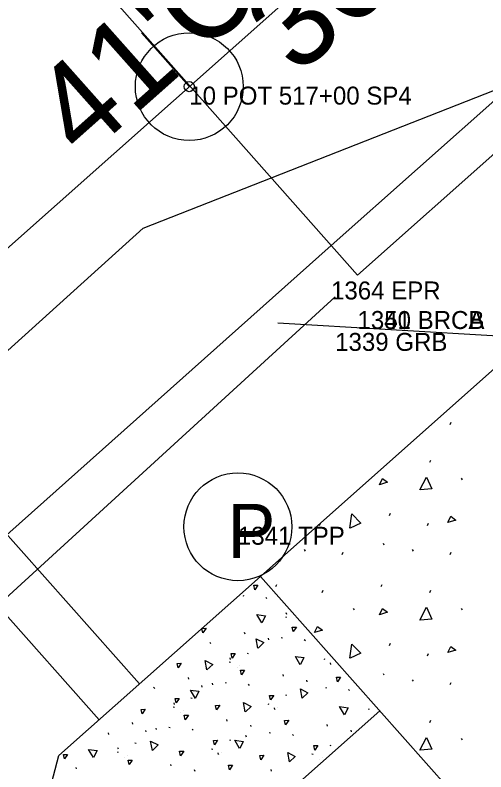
# Model space of a CAD drawing. Extents: x 50001 to 56005, y 49075 to 53926.
# Drawn here: x 53432.14 to 53458.33, y 51442.52 to 51484.63 of the extents above; entities that cross this region are included whole.
import ezdxf

# ---------------------------------------------------------------- set-up
doc = ezdxf.new("R2010")
doc.units = 0
for name, color, linetype in [('Level 1', 7, 'Continuous'), ('Level 15', 7, 'Continuous'), ('Level 18', 7, 'Continuous'), ('Level 20', 7, 'Continuous'), ('Level 3', 7, 'Continuous'), ('Level 5', 7, 'Continuous'), ('Level 51', 7, 'Continuous'), ('Level 53', 7, 'Continuous'), ('Level 55', 7, 'Continuous'), ('Level 57', 7, 'Continuous'), ('Level 59', 7, 'Continuous'), ('Level 7', 7, 'Continuous'), ('Level 8', 7, 'Continuous'), ('Level 9', 7, 'Continuous')]:
    doc.layers.add(name, color=color, linetype=linetype)

# ---------------------------------------------------------------- blocks, each defined once
blk = doc.blocks.new('PC')
at = {"layer": 'Level 1'}
for radius in [3, 0.282]:
    blk.add_circle((0, 0), radius, dxfattribs=at)
blk = doc.blocks.new('TPP')
at = {"layer": 'Level 9'}
blk.add_circle((0, 0), 3, dxfattribs=at)
blk.add_text('P', height=3, dxfattribs=at).set_placement((-0.589, -1.729))

msp = doc.modelspace()

# ---------------------------------------------------------------- linework, layer by layer
at = {"layer": 'Level 1'}
for p, q in [((52544.807, 50683.302), (55534.583, 53340.862)), ((53441.831, 51480.651), (53439.174, 51483.64))]:
    msp.add_line(p, q, dxfattribs=at)
at = {"layer": 'Level 15'}
for p, q in [((53446.758, 51467.502), (53460.734, 51466.679)), ((53445.785, 51453.392), (53460.734, 51466.679)), ((53456.338, 51461.856), (53456.394, 51461.981)), ((53455.214, 51459.747), (53455.27, 51459.872)), ((53456.949, 51458.859), (53457.004, 51458.776)), ((53452.967, 51456.792), (53453.022, 51456.917)), ((53449.076, 51456.223), (53449.131, 51456.348)), ((53455.076, 51456.223), (53455.131, 51456.348)), ((53452.608, 51455.238), (53452.663, 51455.155)), ((53448.227, 51454.885), (53448.282, 51454.802)), ((53450.338, 51454.614), (53450.394, 51454.738)), ((53454.227, 51454.885), (53454.282, 51454.802)), ((53456.338, 51454.614), (53456.394, 51454.738)), ((53475.017, 51420.506), (53445.785, 51453.392)), ((53446.646, 51452.824), (53446.701, 51452.949)), ((53449.214, 51452.505), (53449.27, 51452.63)), ((53452.503, 51452.824), (53452.558, 51452.949)), ((53455.214, 51452.505), (53455.27, 51452.63)), ((53450.949, 51451.617), (53451.004, 51451.534)), ((53456.949, 51451.617), (53457.004, 51451.534)), ((53452.967, 51449.549), (53453.022, 51449.674)), ((53455.076, 51448.98), (53455.131, 51449.105)), ((53452.608, 51447.996), (53452.663, 51447.912)), ((53454.227, 51447.643), (53454.282, 51447.559)), ((53456.338, 51447.371), (53456.394, 51447.496)), ((53455.214, 51445.262), (53455.27, 51445.387)), ((53456.949, 51444.374), (53457.004, 51444.291))]:
    msp.add_line(p, q, dxfattribs=at)
for points in [[(53454.663, 51458.209), (53455.037, 51458.916), (53455.329, 51458.264), (53454.676, 51458.209)], [(53452.406, 51458.499), (53452.572, 51458.846), (53452.85, 51458.637), (53452.406, 51458.499)], [(53450.764, 51456.08), (53450.874, 51456.873), (53451.371, 51456.359), (53450.777, 51456.084)], [(53456.219, 51456.393), (53456.385, 51456.74), (53456.663, 51456.532), (53456.219, 51456.393)], [(53452.406, 51451.256), (53452.572, 51451.603), (53452.85, 51451.395), (53452.406, 51451.256)], [(53454.663, 51450.966), (53455.037, 51451.674), (53455.329, 51451.022), (53454.676, 51450.966)], [(53448.801, 51450.264), (53448.967, 51450.611), (53449.245, 51450.403), (53448.801, 51450.264)], [(53450.764, 51448.837), (53450.874, 51449.63), (53451.371, 51449.117), (53450.777, 51448.842)], [(53456.219, 51449.151), (53456.385, 51449.497), (53456.663, 51449.289), (53456.219, 51449.151)], [(53454.663, 51443.724), (53455.037, 51444.431), (53455.329, 51443.779), (53454.676, 51443.724)]]:
    msp.add_lwpolyline(points, dxfattribs=at)
at = {"layer": 'Level 18'}
for p, q in [((53439.259, 51472.776), (53468.056, 51484.091)), ((53402.158, 51439.255), (53439.259, 51472.776))]:
    msp.add_line(p, q, dxfattribs=at)
at = {"layer": 'Level 20'}
msp.add_line((52706.174, 50782.585), (53452.429, 51445.918), dxfattribs=at)
at = {"layer": 'Level 3'}
for p, q in [((53449.718, 51471.806), (53898.742, 51870.567)), ((53179.352, 51230.724), (53449.718, 51471.806))]:
    msp.add_line(p, q, dxfattribs=at)
at = {"layer": 'Level 5'}
for p, q in [((53900.074, 51869.402), (53451.19, 51470.163)), ((53451.19, 51470.163), (53432.563, 51491.203))]:
    msp.add_line(p, q, dxfattribs=at)
at = {"layer": 'Level 7'}
msp.add_line((53424.8, 51445.953), (53449.946, 51468.944), dxfattribs=at)
at = {"layer": 'Level 8'}
for p, q in [((53439.059, 51447.413), (53426.275, 51461.794)), ((53436.816, 51445.42), (53424.28, 51459.523)), ((53445.785, 51453.392), (53434.574, 51443.427)), ((53444.806, 51452.333), (53444.87, 51452.313)), ((53446.091, 51452.225), (53446.15, 51452.165)), ((53447.249, 51451.275), (53447.225, 51451.363)), ((53447.179, 51451.14), (53447.242, 51451.12)), ((53444.93, 51450.18), (53444.907, 51450.269)), ((53442.969, 51449.724), (53443.028, 51449.665)), ((53446.258, 51449.869), (53446.235, 51449.957)), ((53446.943, 51450), (53447.007, 51449.979)), ((53448.228, 51449.891), (53448.287, 51449.832)), ((53444.126, 51448.775), (53444.103, 51448.863)), ((53445.046, 51449.13), (53445.11, 51449.11)), ((53449.315, 51448.807), (53449.379, 51448.786)), ((53444.056, 51448.64), (53444.12, 51448.619)), ((53444.619, 51448.416), (53444.619, 51448.416)), ((53449.709, 51448.488), (53449.686, 51448.577)), ((53444.489, 51448.311), (53444.489, 51448.311)), ((53441.808, 51447.68), (53441.785, 51447.768)), ((53447.067, 51447.847), (53447.044, 51447.935)), ((53448.394, 51447.536), (53448.371, 51447.624)), ((53439.846, 51447.224), (53439.906, 51447.165)), ((53442.548, 51447.239), (53442.525, 51447.327)), ((53443.136, 51447.369), (53443.112, 51447.457)), ((53443.821, 51447.499), (53443.884, 51447.479)), ((53445.105, 51447.391), (53445.165, 51447.332)), ((53449.403, 51447.213), (53449.467, 51447.192)), ((53447.183, 51446.797), (53447.246, 51446.777)), ((53450.688, 51447.104), (53450.747, 51447.045)), ((53441.004, 51446.275), (53440.981, 51446.363)), ((53441.924, 51446.63), (53441.987, 51446.61)), ((53446.193, 51446.306), (53446.257, 51446.286)), ((53440.934, 51446.139), (53440.998, 51446.119)), ((53441.496, 51445.915), (53441.496, 51445.915)), ((53446.587, 51445.988), (53446.564, 51446.076)), ((53446.625, 51445.978), (53446.625, 51445.978)), ((53446.755, 51446.082), (53446.755, 51446.082)), ((53451.776, 51446.02), (53451.839, 51445.999)), ((53441.366, 51445.811), (53441.366, 51445.811)), ((53438.686, 51445.18), (53438.662, 51445.268)), ((53443.944, 51445.347), (53443.921, 51445.435)), ((53445.272, 51445.035), (53445.249, 51445.124)), ((53449.527, 51445.06), (53449.504, 51445.148)), ((53437.351, 51444.597), (53437.328, 51444.685)), ((53439.426, 51444.738), (53439.403, 51444.826)), ((53440.013, 51444.868), (53439.99, 51444.957)), ((53440.698, 51444.999), (53440.762, 51444.979)), ((53441.983, 51444.891), (53442.042, 51444.832)), ((53446.281, 51444.712), (53446.345, 51444.692)), ((53447.566, 51444.604), (53447.625, 51444.545)), ((53450.855, 51444.749), (53450.832, 51444.837)), ((53444.06, 51444.297), (53444.124, 51444.277)), ((53445.008, 51444.452), (53444.985, 51444.54)), ((53437.882, 51443.774), (53437.859, 51443.863)), ((53438.801, 51444.13), (53438.865, 51444.11)), ((53443.071, 51443.806), (53443.134, 51443.786)), ((53449.643, 51444.01), (53449.707, 51443.99)), ((53430.007, 51425.987), (53434.574, 51443.427)), ((53437.812, 51443.639), (53437.875, 51443.619)), ((53438.374, 51443.415), (53438.374, 51443.415)), ((53443.464, 51443.488), (53443.441, 51443.576)), ((53443.503, 51443.478), (53443.503, 51443.478)), ((53443.633, 51443.582), (53443.633, 51443.582)), ((53448.653, 51443.519), (53448.717, 51443.499)), ((53438.244, 51443.311), (53438.244, 51443.311)), ((53440.822, 51442.847), (53440.799, 51442.935)), ((53449.086, 51443.191), (53449.086, 51443.191)), ((53449.216, 51443.295), (53449.216, 51443.295)), ((53435.563, 51442.68), (53435.54, 51442.768)), ((53442.15, 51442.535), (53442.127, 51442.623)), ((53446.405, 51442.56), (53446.382, 51442.648))]:
    msp.add_line(p, q, dxfattribs=at)
for points in [[(53445.478, 51452.653), (53445.42, 51452.903), (53445.651, 51452.91), (53445.478, 51452.653)], [(53445.868, 51450.809), (53445.595, 51451.268), (53446.068, 51451.208), (53445.873, 51450.817)], [(53442.592, 51450.252), (53442.534, 51450.502), (53442.766, 51450.509), (53442.592, 51450.252)], [(53447.615, 51450.32), (53447.557, 51450.57), (53447.788, 51450.577), (53447.615, 51450.32)], [(53445.649, 51449.402), (53445.55, 51449.926), (53445.973, 51449.709), (53445.657, 51449.408)], [(53444.217, 51448.851), (53444.159, 51449.101), (53444.39, 51449.108), (53444.217, 51448.851)], [(53448.005, 51448.476), (53447.732, 51448.934), (53448.204, 51448.874), (53448.01, 51448.484)], [(53441.212, 51448.3), (53441.154, 51448.55), (53441.385, 51448.557), (53441.212, 51448.3)], [(53442.808, 51448.189), (53442.708, 51448.713), (53443.132, 51448.495), (53442.815, 51448.195)], [(53444.729, 51447.919), (53444.671, 51448.169), (53444.902, 51448.176), (53444.729, 51447.919)], [(53450.075, 51447.533), (53450.017, 51447.783), (53450.248, 51447.79), (53450.075, 51447.533)], [(53448.11, 51446.615), (53448.01, 51447.14), (53448.433, 51446.922), (53448.117, 51446.621)], [(53442.168, 51446.603), (53441.895, 51447.062), (53442.367, 51447.002), (53442.173, 51446.611)], [(53446.354, 51446.518), (53446.296, 51446.768), (53446.527, 51446.775), (53446.354, 51446.518)], [(53441.095, 51446.351), (53441.037, 51446.601), (53441.268, 51446.608), (53441.095, 51446.351)], [(53444.945, 51445.856), (53444.845, 51446.38), (53445.268, 51446.162), (53444.952, 51445.862)], [(53439.209, 51445.745), (53439.152, 51445.995), (53439.383, 51446.002), (53439.209, 51445.745)], [(53443.349, 51445.966), (53443.291, 51446.216), (53443.522, 51446.224), (53443.349, 51445.966)], [(53450.465, 51445.689), (53450.192, 51446.147), (53450.665, 51446.087), (53450.47, 51445.697)], [(53441.607, 51445.418), (53441.549, 51445.668), (53441.78, 51445.676), (53441.607, 51445.418)], [(53447.19, 51445.132), (53447.132, 51445.382), (53447.363, 51445.389), (53447.19, 51445.132)], [(53439.78, 51443.708), (53439.68, 51444.232), (53440.103, 51444.014), (53439.787, 51443.714)], [(53443.231, 51444.017), (53443.174, 51444.267), (53443.405, 51444.275), (53443.231, 51444.017)], [(53444.629, 51443.816), (53444.355, 51444.275), (53444.828, 51444.215), (53444.633, 51443.824)], [(53436.502, 51443.308), (53436.228, 51443.767), (53436.701, 51443.707), (53436.506, 51443.316)], [(53448.814, 51443.731), (53448.756, 51443.981), (53448.987, 51443.988), (53448.814, 51443.731)], [(53434.885, 51443.233), (53434.827, 51443.483), (53435.058, 51443.49), (53434.885, 51443.233)], [(53441.346, 51443.411), (53441.288, 51443.661), (53441.519, 51443.669), (53441.346, 51443.411)], [(53445.809, 51443.18), (53445.751, 51443.429), (53445.983, 51443.437), (53445.809, 51443.18)], [(53447.405, 51443.069), (53447.305, 51443.593), (53447.729, 51443.375), (53447.412, 51443.075)], [(53438.485, 51442.918), (53438.427, 51443.168), (53438.658, 51443.175), (53438.485, 51442.918)], [(53444.067, 51442.632), (53444.009, 51442.881), (53444.24, 51442.889), (53444.067, 51442.632)]]:
    msp.add_lwpolyline(points, dxfattribs=at)

# ---------------------------------------------------------------- block references
at = {"layer": 'Level 1'}
msp.add_blockref('PC', (53441.83, 51480.65), dxfattribs=at)
at = {"layer": 'Level 9'}
msp.add_blockref('TPP', (53444.535, 51456.156), dxfattribs=at)

# ---------------------------------------------------------------- texts
at = {"layer": 'Level 18'}
for s, p in [("36'C", (53447.837, 51481.188)), ("41'C", (53435.938, 51476.513))]:
    msp.add_text(s, height=5, rotation=41.6334, dxfattribs=at).set_placement(p)
at = {"layer": 'Level 51'}
msp.add_text('10 POT 517+00 SP4', height=1, dxfattribs=at).set_placement((53441.83, 51479.65))
at = {"layer": 'Level 53'}
msp.add_text('1364 EPR', height=1, dxfattribs=at).set_placement((53449.718, 51468.806))
at = {"layer": 'Level 55'}
for s in ['1340 BRCA', '1351 BRCB']:
    msp.add_text(s, height=1, dxfattribs=at).set_placement((53451.19, 51467.163))
at = {"layer": 'Level 57'}
msp.add_text('1339 GRB', height=1, dxfattribs=at).set_placement((53449.946, 51465.944))
at = {"layer": 'Level 59'}
msp.add_text('1341 TPP', height=1, dxfattribs=at).set_placement((53444.535, 51455.156))

doc.saveas('drawing.dxf')
